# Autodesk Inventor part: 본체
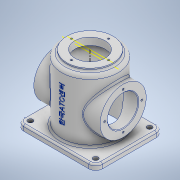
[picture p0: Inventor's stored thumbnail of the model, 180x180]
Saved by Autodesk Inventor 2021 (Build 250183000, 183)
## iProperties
Created: 2021-02
Part Number: 본체
Material: 알루미늄 6061
Document SubType Name: Modeling
Designer: mdu2-97
Density: 2.7 g/cm^3
Appearance: 알루미늄 - 평지
Mass: 1234.41 g
Surface Area: 1072.03 cm^2
Volume: 457.188 cm^3
Author: mdu2-97
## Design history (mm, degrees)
sketch "스케치1"
  geometry: C1 r 50 at (0, 0); 1 further point
  constraints: 1 centre point, 1 coincident
  dimensions: "d0" = 100 diameter of C1
extrude "돌출1" new body sketch "스케치1" distance "d1" = 110; taper "d2" = 0 deg
sketch "스케치2"
  geometry: C1 r 41 at (0, 0); 1 further point
  constraints: 1 centre point, 1 coincident
  dimensions: "d3" = 82 diameter of C1
extrude "돌출2" join sketch "스케치2" distance "d4" = 5; taper "d5" = 0 deg
sketch "스케치3"
  geometry: L1 (50, 110)-(-50, 110) reference; L2 (50, 0)-(-50, 0) reference; 1 further point
  node "투영된 루프1"
sketch "스케치5"
  geometry: L1 (41, 115)-(-41, 115) reference; L2 (0, 115)-(0, 0); L3 (50, 0)-(-50, 0) reference
  constraints: 2 end point, 1 midpoint, 1 perpendicular
node "작업 평면1"
sketch "스케치6"
  geometry: L1 (119.427, 0)-(-19.427, 0); C1 r 41 at (50, 0); 2 further points
  constraints: 2 end point, 1 centre point, 1 coincident, 1 horizontal, 1 midpoint
  dimensions: "d14" = 82 diameter of C1; "d15" = 50 distance of point (0, 0) C1.centre
extrude "돌출3" join sketch "스케치6" extent not by distance; stored distance "d16" = 0; taper "d17" = 0 deg
sketch "스케치7"
  geometry: C1 r 27 at (0, 0); 1 further point
  constraints: 1 centre point
  dimensions: "d18" = 54 diameter of C1
extrude "돌출4" cut sketch "스케치7" extent not by distance; stored distance "d19" = 0; taper "d20" = 0 deg
sketch "스케치8"
  geometry: C1 r 50 at (0, 0) reference; 1 further point
sketch "스케치9"
  geometry: L1 (-70, -60)-(70, -60); L2 (70, -60)-(70, 60); L3 (70, 60)-(-70, 60); L4 (-70, 60)-(-70, -60); L5 (-70, -60)-(70, 60); L6 (70, -60)-(-70, 60); 1 further point
  constraints: 12 end point, 2 midpoint, 2 parallel, 1 horizontal, 1 perpendicular
  dimensions: "d21" = 140 distance of L3.end L2.end; "d22" = 120 distance of L2.end L1.end
extrude "돌출5" join sketch "스케치9" distance "d23" = 10; taper "d24" = 0 deg
sketch "스케치10"
  geometry: C1 r 50 at (0, 0) reference; 1 further point
hole "구멍2" sketch "스케치10" at (0, 0) diameter "d25" = 54; stored, may be unused: countersink angle "d29" = 90 deg, drill point angle "d31" = 0 deg; dims "d26" = 7, "d27" = 84, "d28" = 112, "d30" = 112
sketch "스케치11"
  geometry: C1 r 27 at (0, 0) reference; C2 r 27 at (0, 0) reference; C3 r 41 at (0, 0) reference; 2 further points
  dimensions: "d32" = 33 distance of point (0, 33) C1.centre
hole "구멍3" sketch "스케치11" at (0, 33) diameter "d33" = 3.242; stored, may be unused: countersink angle "d37" = 90 deg, drill point angle "d39" = 118 deg; dims "d34" = 8, "d35" = 84, "d36" = 112, "d38" = 10
sketch "스케치12"
  geometry: 2 further points
  dimensions: "d43" = 33 distance of point (0, 33) point (0, 0)
hole "구멍4" sketch "스케치12" at (0, 33) diameter "d44" = 3.242; stored, may be unused: countersink angle "d48" = 90 deg, drill point angle "d50" = 118 deg; dims "d45" = 8, "d46" = 84, "d47" = 112, "d49" = 10
fillet "모깎기1" dims "d63" = 6
chamfer "모따기1" distance "d64" = 1; stored, may be unused: second distance "d65" = 2, angle "d66" = 45 deg
fillet "모깎기2" dims "d67" = 3
fillet "모깎기3" dims "d68" = 12
sketch "스케치14"
  geometry: A1 r 12 centre (-58, 48) between (-58, 60) and (-70, 48) reference; A2 r 12 centre (58, 48) between (70, 48) and (58, 60) reference; A3 r 12 centre (58, -48) between (58, -60) and (70, -48) reference; A4 r 12 centre (-58, -48) between (-70, -48) and (-58, -60) reference; 1 further point
hole "구멍6" sketch "스케치14" at (58, -48), (58, 48), (-58, -48), (-58, 48) diameter "d69" = 9; stored, may be unused: countersink angle "d73" = 90 deg, drill point angle "d75" = 0 deg; dims "d70" = 8, "d71" = 84, "d72" = 112, "d74" = 10
fillet "모깎기4" dims "d76" = 3
fillet "모깎기5" dims "d77" = 3
node "작업 평면2"
sketch "스케치15"
  geometry: L1 (58, -10)-(-58, -10) reference; 2 further points
  constraints: 1 vertical alignment, 1 other
  dimensions: "d79" = 66 distance from line of L1 point (0, 56)
feature "엠보싱1" sketch "스케치15" dims "d1" = 110, "d80" = 0.5, "d81" = 0
fillet "모깎기6" dims "d82" = 3
node "솔리드1"
mirror "미러1"
pattern_circular "원형 패턴1" dims angle "d41" = 360 deg
mirror "미러2"
pattern_circular "원형 패턴2" dims angle "d52" = 360 deg
node "투영된 루프2"
feature "A9D066F2-1C7D-4E18-AEED-F7BC21143FA4" dims "d25" = 54, "d26" = 7, "d27" = 84, "d28" = 112, "d29" = 90 deg, "d30" = 112, "d31" = 0
other parameters: "d13" = 59, "d78" = 57.75
